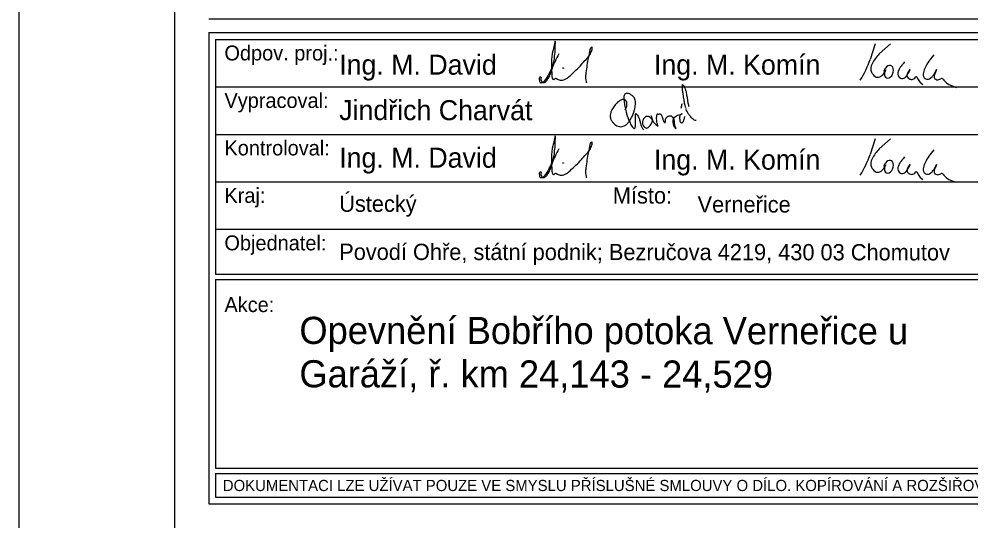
# Model space of a CAD drawing. Extents: x 67.3 to 115.4, y -93.9 to -78.3.
# Drawn here: x 67.26 to 74.28, y -86.38 to -82.68 of the extents above; entities that cross this region are included whole.
import ezdxf

# ---------------------------------------------------------------- set-up
doc = ezdxf.new("R2010")
doc.units = 0
for name, color, linetype in [('07_rozpiska', 7, 'Continuous'), ('07_rámeček', 7, 'Continuous'), ('Default', 7, 'Continuous'), ('Rozpiska + rámeček', 7, 'Continuous')]:
    doc.layers.add(name, color=color, linetype=linetype)

# ---------------------------------------------------------------- blocks, each defined once
blk = doc.blocks.new('Charvat')
at = {"layer": 'Rozpiska + rámeček'}
for points in [[(0.0826, 0.02), (0.0817, 0.0228), (0.0806, 0.0281), (0.0796, 0.0345), (0.0789, 0.0395), (0.0784, 0.0445), (0.0784, 0.0456), (0.0785, 0.0469), (0.0787, 0.0476), (0.0791, 0.0473), (0.0804, 0.0456), (0.0816, 0.0427), (0.0827, 0.0394), (0.0832, 0.0363), (0.0841, 0.0314), (0.0846, 0.0282), (0.0855, 0.0238), (0.086, 0.0216)], [(0.0108, 0.0178), (0.0123, 0.0208), (0.0129, 0.0234), (0.0122, 0.0279), (0.0108, 0.0294), (0.0087, 0.0301), (0.0059, 0.0293), (0.0024, 0.0271), (-0.0017, 0.0225), (-0.0049, 0.0177), (-0.0062, 0.0145), (-0.0067, 0.0115), (-0.0063, 0.0075), (-0.0059, 0.0064), (-0.0039, 0.0034), (-0.0014, 0.0007), (0.001, -0.001), (0.0043, -0.0019), (0.0075, -0.0019), (0.0097, -0.001), (0.0131, 0.0013), (0.0158, 0.0045), (0.0192, 0.0101), (0.022, 0.0182), (0.0223, 0.0193), (0.023, 0.0256), (0.0227, 0.0293), (0.0219, 0.0315), (0.0199, 0.034), (0.017, 0.036), (0.0147, 0.0371), (0.0142, 0.0372), (0.013, 0.0373), (0.0113, 0.0368), (0.0106, 0.0362), (0.0097, 0.0348), (0.0095, 0.0343), (0.0093, 0.0333), (0.0093, 0.0314), (0.0096, 0.0279), (0.0105, 0.0221), (0.012, 0.0151), (0.0133, 0.0108), (0.0166, 0.0023), (0.0195, -0.0026), (0.0202, -0.0035), (0.0214, -0.0042), (0.022, -0.0042), (0.0225, -0.0034), (0.023, -0.0014), (0.0231, 0), (0.0231, 0.0051), (0.0231, 0.0111), (0.0231, 0.0124), (0.0233, 0.0132), (0.0236, 0.0135), (0.024, 0.0133), (0.0254, 0.0115), (0.0268, 0.0092), (0.0279, 0.0059), (0.0289, 0.0018), (0.0298, -0.0012), (0.0315, -0.0041), (0.0327, -0.0059)], [(0.0771, 0.0198), (0.0779, 0.024), (0.0784, 0.0252)], [(0.0428, 0.0062), (0.0417, 0.0075), (0.0401, 0.009), (0.0394, 0.0095), (0.0378, 0.0101), (0.0368, 0.0101), (0.0353, 0.0098), (0.034, 0.0088), (0.0326, 0.0071), (0.0316, 0.0051), (0.0313, 0.0026), (0.0313, 0.0011), (0.0322, -0.0007), (0.0338, -0.0025), (0.0354, -0.0034), (0.0366, -0.0037), (0.0381, -0.0031), (0.0397, -0.0014), (0.0411, 0.0004), (0.0422, 0.0025), (0.043, 0.005), (0.043, 0.0063), (0.0429, 0.0069), (0.0424, 0.0086), (0.0414, 0.0106), (0.0421, 0.009), (0.0433, 0.0053), (0.0444, 0.0034), (0.0458, 0.0017), (0.0476, 0), (0.0497, -0.0015), (0.0498, -0.0016), (0.0499, -0.0016), (0.0499, -0.0014), (0.0492, 0.0003), (0.0487, 0.0022), (0.0482, 0.0055), (0.048, 0.0086), (0.0484, 0.0114), (0.0491, 0.0131), (0.0493, 0.013), (0.0506, 0.0127), (0.0522, 0.0131), (0.0539, 0.0111), (0.0547, 0.0094), (0.0552, 0.0074), (0.0556, 0.0056), (0.0566, 0.0038), (0.058, 0.0025), (0.0582, 0.0031), (0.0585, 0.0057), (0.0589, 0.0076), (0.0593, 0.0083), (0.0604, 0.0095), (0.0616, 0.0102), (0.0632, 0.0106), (0.065, 0.0106), (0.0665, 0.0094), (0.0678, 0.0078), (0.0686, 0.0033), (0.0691, 0.0001), (0.0701, -0.0031), (0.0705, -0.0044), (0.0697, -0.0035), (0.0682, -0.0005), (0.0677, 0.0025), (0.0677, 0.0059), (0.0683, 0.0079), (0.0702, 0.01), (0.0728, 0.0114), (0.0756, 0.0122), (0.0781, 0.0133), (0.0764, 0.0125), (0.0755, 0.0112), (0.0751, 0.0096), (0.0751, 0.0075), (0.0753, 0.005), (0.0753, 0.0048), (0.0758, 0.0038), (0.0766, 0.003), (0.0772, 0.0026), (0.0776, 0.0025), (0.0783, 0.0027), (0.0791, 0.0034), (0.0799, 0.0047), (0.0806, 0.0069), (0.0816, 0.0104)], [(0.0947, 0.0053), (0.0934, 0.0053), (0.0921, 0.0059), (0.0901, 0.0076), (0.0883, 0.0095), (0.0858, 0.0127), (0.0839, 0.0159), (0.0829, 0.0186), (0.0827, 0.0193)]]:
    blk.add_spline(points, degree=3, dxfattribs=at)

msp = doc.modelspace()

# ---------------------------------------------------------------- linework, layer by layer
at = {"layer": '07_rozpiska'}
msp.add_line((77.2554, -82.6813), (68.6554, -82.6813), dxfattribs=at)
for points in [[(71.2105, -82.8729), (71.2118, -82.8631), (71.2111, -82.8434), (71.2033, -82.8742), (71.193, -82.9163), (71.1868, -82.9425), (71.1836, -82.9862), (71.182, -83.0219), (71.1852, -83.0964), (71.1884, -83.1161), (71.2011, -83.1278), (71.2056, -83.1246), (71.2066, -83.1223), (71.2137, -83.1174), (71.2263, -83.1239), (71.24, -83.1294), (71.2549, -83.132), (71.273, -83.1291), (71.2934, -83.1207), (71.32, -83.0993), (71.3637, -83.0582), (71.4039, -83.017), (71.4379, -82.9785), (71.4654, -82.9451), (71.4803, -82.9121), (71.4839, -82.8959), (71.4826, -82.8891), (71.4764, -82.8904), (71.4657, -82.9137), (71.4599, -82.9376), (71.4512, -82.9794), (71.4424, -83.0351), (71.4353, -83.0912), (71.4346, -83.12), (71.4382, -83.1417), (71.4401, -83.1524)], [(71.2043, -82.9781), (71.2063, -82.9522), (71.2088, -82.9296), (71.2108, -82.9053), (71.2105, -82.8729)], [(71.0958, -83.1333), (71.0939, -83.1216), (71.0948, -83.1139), (71.0997, -83.1074), (71.1033, -83.1067), (71.1052, -83.1187), (71.1058, -83.133), (71.1139, -83.1453), (71.1253, -83.1495), (71.136, -83.1456), (71.1454, -83.1378), (71.1505, -83.131), (71.1658, -83.1067), (71.1719, -83.0951), (71.1878, -83.0488), (71.2043, -82.9781)], [(71.2367, -82.9386), (71.2092, -82.9934), (71.1629, -83.0854), (71.1295, -83.1398), (71.1172, -83.1511), (71.1078, -83.1527), (71.102, -83.1521), (71.0977, -83.1453), (71.0958, -83.1333)], [(71.2691, -83.0403), (71.2668, -83.0413), (71.2668, -83.0433), (71.2685, -83.0442), (71.2717, -83.0449), (71.2723, -83.0433), (71.2723, -83.0416), (71.2691, -83.0403)], [(71.2105, -83.5729), (71.2118, -83.5631), (71.2111, -83.5434), (71.2033, -83.5742), (71.193, -83.6163), (71.1868, -83.6425), (71.1836, -83.6862), (71.182, -83.7219), (71.1852, -83.7964), (71.1884, -83.8161), (71.2011, -83.8278), (71.2056, -83.8246), (71.2066, -83.8223), (71.2137, -83.8174), (71.2263, -83.8239), (71.24, -83.8294), (71.2549, -83.832), (71.273, -83.8291), (71.2934, -83.8207), (71.32, -83.7993), (71.3637, -83.7582), (71.4039, -83.717), (71.4379, -83.6785), (71.4654, -83.6451), (71.4803, -83.6121), (71.4839, -83.5959), (71.4826, -83.5891), (71.4764, -83.5904), (71.4657, -83.6137), (71.4599, -83.6376), (71.4512, -83.6794), (71.4424, -83.7351), (71.4353, -83.7912), (71.4346, -83.82), (71.4382, -83.8417), (71.4401, -83.8524)], [(71.2043, -83.6781), (71.2063, -83.6522), (71.2088, -83.6296), (71.2108, -83.6053), (71.2105, -83.5729)], [(71.0958, -83.8333), (71.0939, -83.8216), (71.0948, -83.8139), (71.0997, -83.8074), (71.1033, -83.8067), (71.1052, -83.8187), (71.1058, -83.833), (71.1139, -83.8453), (71.1253, -83.8495), (71.136, -83.8456), (71.1454, -83.8378), (71.1505, -83.831), (71.1658, -83.8067), (71.1719, -83.7951), (71.1878, -83.7488), (71.2043, -83.6781)], [(71.2367, -83.6386), (71.2092, -83.6934), (71.1629, -83.7854), (71.1295, -83.8398), (71.1172, -83.8511), (71.1078, -83.8527), (71.102, -83.8521), (71.0977, -83.8453), (71.0958, -83.8333)], [(71.2691, -83.7403), (71.2668, -83.7413), (71.2668, -83.7433), (71.2685, -83.7442), (71.2717, -83.7449), (71.2723, -83.7433), (71.2723, -83.7416), (71.2691, -83.7403)]]:
    msp.add_spline(points, degree=3, dxfattribs=at)
at = {"layer": 'Default'}
for p, q in [((73.6352, -83.0799), (73.6496, -83.054)), ((73.8771, -83.1087), (73.8872, -83.126)), ((73.9088, -83.1548), (73.9203, -83.1663)), ((73.6352, -83.7799), (73.6496, -83.754)), ((73.8771, -83.8087), (73.8872, -83.826)), ((73.9088, -83.8548), (73.9203, -83.8663))]:
    msp.add_line(p, q, dxfattribs=at)
for points in [[(73.5704, -82.8639), (73.5344, -82.9791)], [(73.6827, -82.8639), (73.5992, -82.9388)], [(74.0024, -82.946), (73.9736, -82.982)], [(73.7576, -83.0367), (73.7547, -83.0396)], [(73.7864, -82.9964), (73.7763, -83.0108)], [(73.8224, -83.0655), (73.8296, -83.054), (73.8195, -83.0655)], [(73.9995, -83.0972), (74.024, -83.054), (74.0139, -83.0799)], [(73.8051, -83.0972), (73.8051, -83.0972)], [(73.808, -83.0799), (73.808, -83.0828)], [(73.5704, -83.5639), (73.5344, -83.6791)], [(73.6827, -83.5639), (73.5992, -83.6388)], [(73.7864, -83.6964), (73.7763, -83.7108)], [(74.0024, -83.646), (73.9736, -83.682)], [(73.7576, -83.7367), (73.7547, -83.7396)], [(73.8224, -83.7655), (73.8296, -83.754), (73.8195, -83.7655)], [(73.9995, -83.7972), (74.024, -83.754), (74.0139, -83.7799)], [(73.8051, -83.7972), (73.8051, -83.7972)], [(73.808, -83.7799), (73.808, -83.7828)]]:
    msp.add_lwpolyline(points, dxfattribs=at)
for centre, radius, start, end in [((72.6011, -82.6324), 0.9948, 329.80858, 339.56815), ((73.8592, -83.1806), 0.3545, 137.00062, 151.51062), ((74.2053, -83.1677), 0.2956, 141.11668, 151.43002), ((73.6116, -83.0472), 0.0732, 150.83631, 201.23374), ((73.7124, -83.0954), 0.084, 133.12102, 160.6603), ((73.6916, -83.0877), 0.0529, 142.82783, 193.29225), ((73.8433, -83.1022), 0.1085, 146.31446, 165.71836), ((73.5134, -82.8822), 0.288, 326.31446, 326.46946), ((73.9981, -83.1936), 0.288, 140.57196, 146.46893), ((73.6545, -82.9865), 0.1862, 320.58833, 335.16259), ((73.9862, -83.0884), 0.0617, 158.78845, 195.14726), ((74.127, -83.1271), 0.2075, 150.931, 162.8917), ((73.6181, -83.0376), 0.083, 205.78195, 234.22418), ((73.5897, -83.074), 0.0369, 236.98468, 294.62862), ((73.6296, -83.1912), 0.0864, 108.04736, 108.08265), ((73.5672, -83.0298), 0.0864, 295.93387, 323.63221), ((73.77, -83.0872), 0.0323, 245.35778, 276.92267), ((73.763, -83.0731), 0.0475, 283.31943, 318.16716), ((73.8338, -83.0942), 0.0288, 154.94151, 187.17365), ((73.8338, -83.0955), 0.0286, 186.45097, 212.31824), ((73.861, -83.104), 0.0576, 139.19606, 154.94016), ((73.8371, -83.0936), 0.0324, 212.08411, 258.70933), ((73.8387, -83.09), 0.0362, 257.35338, 296.27075), ((73.8324, -83.0858), 0.043, 301.37529, 327.02531), ((73.8734, -83.1121), 0.00576, 26.63136, 150.41952), ((73.9647, -83.0885), 0.0864, 206.63144, 229.82938), ((73.9519, -83.0965), 0.0265, 197.61582, 249.38851), ((73.9583, -83.0778), 0.0463, 250.12564, 275.82035), ((73.959, -83.089), 0.035, 276.59581, 304.89281), ((73.9172, -83.0405), 0.099, 308.6573, 325.5075), ((74.0344, -83.1029), 0.0297, 172.16185, 218.17447), ((74.0714, -83.1117), 0.0677, 151.17648, 169.00349), ((74.0335, -83.0945), 0.0349, 229.93747, 256.22885), ((74.0297, -83.0829), 0.0458, 264.36538, 302.31991), ((74.0613, -83.1331), 0.0136, 38.96313, 121.674), ((74.1807, -83.0484), 0.1329, 214.99845, 231.36881), ((74.2172, -82.9828), 0.2073, 234.79421, 256.99308), ((72.6011, -83.3324), 0.9948, 329.80858, 339.56815), ((73.8592, -83.8806), 0.3545, 137.00062, 151.51062), ((74.2053, -83.8677), 0.2956, 141.11668, 151.43002), ((73.6116, -83.7472), 0.0732, 150.83631, 201.23374), ((73.7124, -83.7954), 0.084, 133.12102, 160.6603), ((73.6916, -83.7877), 0.0529, 142.82783, 193.29225), ((73.8433, -83.8022), 0.1085, 146.31446, 165.71836), ((73.5134, -83.5822), 0.288, 326.31446, 326.46946), ((73.9981, -83.8936), 0.288, 140.57196, 146.46893), ((73.6545, -83.6865), 0.1862, 320.58833, 335.16259), ((73.861, -83.804), 0.0576, 139.19606, 154.94016), ((73.9862, -83.7884), 0.0617, 158.78845, 195.14726), ((74.127, -83.8271), 0.2075, 150.931, 162.8917), ((73.6181, -83.7376), 0.083, 205.78195, 234.22418), ((73.5897, -83.774), 0.0369, 236.98468, 294.62862), ((73.6296, -83.8912), 0.0864, 108.04736, 108.08265), ((73.5672, -83.7298), 0.0864, 295.93387, 323.63221), ((73.77, -83.7872), 0.0323, 245.35778, 276.92267), ((73.763, -83.7731), 0.0475, 283.31943, 318.16716), ((73.8338, -83.7942), 0.0288, 154.94151, 187.17365), ((73.8338, -83.7955), 0.0286, 186.45097, 212.31824), ((73.8371, -83.7936), 0.0324, 212.08411, 258.70933), ((73.8387, -83.79), 0.0362, 257.35338, 296.27075), ((73.8324, -83.7858), 0.043, 301.37529, 327.02531), ((73.8734, -83.8121), 0.00576, 26.63136, 150.41952), ((73.9647, -83.7885), 0.0864, 206.63144, 229.82938), ((73.9519, -83.7965), 0.0265, 197.61582, 249.38851), ((73.9583, -83.7778), 0.0463, 250.12564, 275.82035), ((73.959, -83.789), 0.035, 276.59581, 304.89281), ((73.9172, -83.7405), 0.099, 308.6573, 325.5075), ((74.0344, -83.8029), 0.0297, 172.16185, 218.17447), ((74.0714, -83.8117), 0.0677, 151.17648, 169.00349), ((74.0335, -83.7945), 0.0349, 229.93747, 256.22885), ((74.0297, -83.7829), 0.0458, 264.36538, 302.31991), ((74.0613, -83.8331), 0.0136, 38.96313, 121.674), ((74.1807, -83.7484), 0.1329, 214.99845, 231.36881), ((74.2172, -83.6828), 0.2073, 234.79421, 256.99308)]:
    msp.add_arc(centre, radius, start, end, dxfattribs=at)
for centre, major_axis, ratio, start_param, end_param in [((73.6711, -83.0696), (0.0152, 0.0459), 0.677007, 2.488228, 7.220838), ((73.7739, -83.0863), (-0.0357, 0.0109), 0.932374, 0, 1.363098), ((73.6711, -83.7696), (0.0152, 0.0459), 0.677007, 2.488228, 7.220838), ((73.7739, -83.7863), (-0.0357, 0.0109), 0.932374, 0, 1.363098)]:
    msp.add_ellipse(centre, major_axis=major_axis, ratio=ratio, start_param=start_param, end_param=end_param, dxfattribs=at)
at = {"layer": 'Rozpiska + rámeček'}
for p, q in [((68.6554, -82.7813), (68.6554, -86.2563)), ((68.6554, -82.7813), (77.2554, -82.7813)), ((68.7054, -82.8313), (68.7054, -84.5613)), ((68.7054, -82.8313), (74.3654, -82.8313)), ((68.7054, -83.1813), (74.3654, -83.1813)), ((68.7054, -83.5313), (74.3654, -83.5313)), ((68.7054, -83.8813), (74.3654, -83.8813)), ((68.7054, -84.2313), (74.3654, -84.2313)), ((68.7054, -84.5613), (74.3654, -84.5613)), ((68.7054, -84.6013), (74.3654, -84.6013)), ((68.7054, -84.6013), (68.7054, -85.9913)), ((68.7054, -85.9913), (74.3654, -85.9913)), ((68.7054, -86.0313), (77.2054, -86.0313)), ((68.7054, -86.0313), (68.7054, -86.2063)), ((68.7054, -86.2063), (77.2054, -86.2063)), ((68.6554, -86.2563), (77.2554, -86.2563))]:
    msp.add_line(p, q, dxfattribs=at)
for points in [[(67.2554, -79.0813), (77.7554, -79.0813), (77.7554, -93.9313), (67.2554, -93.9313)], [(68.4054, -79.0813), (77.5054, -79.0813), (77.5054, -86.5063), (68.4054, -86.5063)]]:
    msp.add_lwpolyline(points, close=True, dxfattribs=at)

# ---------------------------------------------------------------- block references
at = {"layer": '07_rámeček', "xscale": 6.250000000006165, "yscale": 6.250000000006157, "rotation": 3.739011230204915e-09}
msp.add_blockref('Charvat', (71.6584, -83.462), dxfattribs=at)

# ---------------------------------------------------------------- texts
at = {"layer": '07_rozpiska'}
for s, p in [('Opevnění Bobřího potoka Verneřice u ', (69.3234, -85.0763)), ('Garáží, ř. km 24,143 - 24,529', (69.3232, -85.3963))]:
    msp.add_text(s, height=0.2, rotation=359.95393, dxfattribs=at).set_placement(p)
at = {"layer": 'Rozpiska + rámeček'}
for s, height, rotation, p in [('Odpov. proj.:', 0.11, 359.95393, (68.7704, -82.9863)), ('Ing. M. David', 0.147465, 359.95278, (69.6171, -83.0907)), ('Ing. M. Komín', 0.147465, 359.95278, (71.9388, -83.0907)), ('Vypracoval:', 0.11, 359.95393, (68.7704, -83.3363)), ('Jindřich Charvát', 0.147465, 359.95278, (69.6171, -83.4263)), ('Kontroloval:', 0.11, 359.95393, (68.7704, -83.6863)), ('Ing. M. David', 0.147465, 359.95278, (69.6171, -83.7763)), ('Ing. M. Komín', 0.147465, 359.95278, (71.9388, -83.7907)), ('Kraj:', 0.11, 359.95393, (68.7704, -84.0363)), ('Ústecký', 0.12, 359.95393, (69.6171, -84.1023)), ('Místo:', 0.12, 359.95393, (71.6354, -84.0413)), ('Verneřice', 0.12, 359.95278, (72.2604, -84.1071)), ('Objednatel:', 0.11, 359.95393, (68.7704, -84.3863)), ('Povodí Ohře, státní podnik; Bezručova 4219, 430 03 Chomutov', 0.12, 359.95278, (69.6171, -84.4571)), ('Akce:', 0.11, 359.95393, (68.7704, -84.8413))]:
    msp.add_text(s, height=height, rotation=rotation, dxfattribs=at).set_placement(p)
msp.add_text('DOKUMENTACI LZE UŽÍVAT POUZE VE SMYSLU PŘÍSLUŠNÉ SMLOUVY O DÍLO. KOPÍROVÁNÍ A ROZŠIŘOVÁNÍ POUZE PO PŘEDCHOZÍM SOUHLASU  AZ CONSULT spol. s. r.o.', height=0.0822563, dxfattribs=at).set_placement((68.7584, -86.1609))

doc.saveas('drawing.dxf')
